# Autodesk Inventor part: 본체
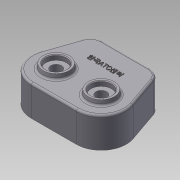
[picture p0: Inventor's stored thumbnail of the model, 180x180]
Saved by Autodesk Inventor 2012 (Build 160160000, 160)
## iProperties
Created: 2014-12
Part Number: 본체
Material: 알루미늄-6061
Document SubType Name: Modeling
Designer: Administrator
Density: 2.71 g/cm^3
Mass: 613.436 g
Surface Area: 665.18 cm^2
Volume: 226.36 cm^3
Author: Administrator
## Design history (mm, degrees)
sketch "스케치1"
  geometry: L1 (0, 36)-(-34.162, 36); L2 (0, 36)-(34.162, 36); L3 (-51.181, 23.862)-(-66.565, -20.803); L4 (51.181, 23.862)-(66.565, -20.803); L5 (32.527, -68.527)-(-32.527, -68.527); A1 r 36 centre (-32.527, -32.527) between (-66.565, -20.803) and (-32.527, -68.527); A2 r 36 centre (32.527, -32.527) between (32.527, -68.527) and (66.565, -20.803); A3 r 18 centre (-34.162, 18) between (-34.162, 36) and (-51.181, 23.862); A4 r 18 centre (34.162, 18) between (51.181, 23.862) and (34.162, 36); 3 further points
  constraints: 10 end point, 8 point on circle, 7 tangent, 4 centre point, 4 point on line, 1 collinear, 1 equal radius, 1 parallel
extrude "돌출1" new body sketch "스케치1" distance "d9" = 44; taper "d10" = 0 deg
sketch "스케치2"
  geometry: L1 (34.162, 31)-(-34.162, 31); L2 (-46.453, 22.233)-(-61.837, -22.432); L3 (-32.527, -63.527)-(32.527, -63.527); L4 (61.837, -22.432)-(46.453, 22.233); A1 r 13 centre (-34.162, 18) between (-34.162, 31) and (-46.453, 22.233); A2 r 31 centre (-32.527, -32.527) between (-61.837, -22.432) and (-32.527, -63.527); A3 r 31 centre (32.527, -32.527) between (32.527, -63.527) and (61.837, -22.432); A4 r 13 centre (34.162, 18) between (46.453, 22.233) and (34.162, 31); 6 further points
  constraints: 8 end point, 8 point on circle, 4 centre point
extrude "돌출2" cut sketch "스케치2" distance "d12" = 34; taper "d13" = 0 deg
sketch "스케치3"
  geometry: C1 r 24 at (0, 0); 1 further point
  constraints: 1 centre point, 1 coincident
  dimensions: "d14" = 48 diameter of C1
extrude "돌출3" join sketch "스케치3" distance "d15" = 11; taper "d16" = 0 deg
sketch "스케치4"
  geometry: C1 r 24 at (0, 0) reference; C2 r 20 at (0, 0)
  constraints: 1 centre point, 1 coincident
  dimensions: "d17" = 40 diameter of C2
extrude "돌출4" cut sketch "스케치4" distance "d18" = 12; taper "d19" = 0 deg
sketch "스케치5"
  geometry: C1 r 20 at (0, 0) reference; C2 r 10 at (0, 0)
  constraints: 1 centre point, 1 coincident
  dimensions: "d20" = 20 diameter of C2
extrude "돌출5" cut sketch "스케치5" distance "d21" = 3; taper "d22" = 0 deg
sketch "스케치6"
  geometry: C1 r 24 at (-32.527, -32.527); A1 r 31 centre (-32.527, -32.527) between (-61.837, -22.432) and (-32.527, -63.527) reference
  constraints: 1 centre point, 1 coincident
  dimensions: "d23" = 48 diameter of C1
extrude "돌출6" join sketch "스케치6" distance "d24" = 11; taper "d25" = 0 deg
sketch "스케치7"
  geometry: C1 r 17.5 at (-32.527, -32.527); A1 r 24 centre (-32.527, -32.527) between (-21.111, -11.416) and (-11.416, -21.111) reference
  constraints: 1 centre point, 1 coincident
  dimensions: "d26" = 35 diameter of C1
extrude "돌출7" cut sketch "스케치7" distance "d27" = 11; taper "d28" = 0 deg
sketch "스케치8"
  geometry: C1 r 24 at (32.527, -32.527); A1 r 31 centre (32.527, -32.527) between (32.527, -63.527) and (61.837, -22.432) reference
  constraints: 1 centre point, 1 coincident
  dimensions: "d29" = 48 diameter of C1
extrude "돌출8" join sketch "스케치8" distance "d30" = 11; taper "d31" = 0 deg
sketch "스케치9"
  geometry: C1 r 17.5 at (32.527, -32.527); A1 r 24 centre (32.527, -32.527) between (11.416, -21.111) and (21.111, -11.416) reference
  constraints: 1 centre point, 1 coincident
  dimensions: "d32" = 35 diameter of C1
extrude "돌출9" cut sketch "스케치9" distance "d33" = 11; taper "d34" = 0 deg
sketch "스케치10"
  geometry: C1 r 20 at (-32.527, -32.527); A1 r 36 centre (-32.527, -32.527) between (-66.565, -20.803) and (-32.527, -68.527) reference; 1 further point
  constraints: 1 centre point, 1 coincident
  dimensions: "d35" = 40 diameter of C1
extrude "돌출10" join sketch "스케치10" distance "d36" = 7; taper "d37" = -10 deg
sketch "스케치11"
  geometry: C1 r 18.766 at (0, 0) reference; C2 r 15 at (0, 0); 1 further point
  constraints: 1 centre point, 1 coincident
  dimensions: "d38" = 30 diameter of C2
extrude "돌출11" cut sketch "스케치11" distance "d39" = 7; taper "d40" = 0 deg
sketch "스케치12"
  geometry: C1 r 15 at (0, 0) reference; C2 r 7.75 at (0, 0); 1 further point
  constraints: 1 centre point, 1 coincident
  dimensions: "d41" = 15.5 diameter of C2
extrude "돌출12" cut sketch "스케치12" distance "d42" = 10; taper "d43" = 0 deg
sketch "스케치13"
  geometry: C1 r 20 at (32.527, -32.527); A1 r 36 centre (32.527, -32.527) between (32.527, -68.527) and (66.565, -20.803) reference; 1 further point
  constraints: 1 centre point, 1 coincident
  dimensions: "d44" = 40 diameter of C1
extrude "돌출13" join sketch "스케치13" distance "d45" = 7; taper "d46" = -10 deg
sketch "스케치14"
  geometry: C1 r 18.766 at (0, 0) reference; C2 r 15 at (0, 0); 1 further point
  constraints: 1 centre point, 1 coincident
  dimensions: "d47" = 30 diameter of C2
extrude "돌출14" cut sketch "스케치14" distance "d48" = 7; taper "d49" = 0 deg
sketch "스케치15"
  geometry: C1 r 15 at (0, 0) reference; C2 r 7.75 at (0, 0); 1 further point
  constraints: 1 centre point, 1 coincident
  dimensions: "d50" = 15.5 diameter of C2
extrude "돌출15" cut sketch "스케치15" distance "d51" = 15.5; taper "d52" = 0 deg
sketch "스케치16"
  geometry: L1 (-32.527, -63.527)-(32.527, -63.527) reference; A1 r 8 centre (0, -63.527) between (8, -63.527) and (-8, -63.527)
  constraints: 2 point on circle, 2 point on line, 1 centre point, 1 midpoint
  dimensions: "d53" = 16 diameter of A1
extrude "돌출16" join sketch "스케치16" distance "d54" = 34; taper "d55" = 0 deg
sketch "스케치17"
  geometry: L1 (61.837, -22.432)-(46.453, 22.233) reference; L2 (-46.453, 22.233)-(-61.837, -22.432) reference; A1 r 8 centre (51.7, 7) between (49.095, 14.564) and (54.305, -0.564); A2 r 8 centre (-51.7, 7) between (-54.305, -0.564) and (-49.095, 14.564)
  constraints: 6 point on line, 4 point on circle, 2 centre point
  dimensions: "d58" = 16 diameter of A1; "d59" = 16 diameter of A2
extrude "돌출17" join sketch "스케치17" distance "d60" = 34; taper "d61" = 0 deg
sketch "스케치18"
  geometry: A1 r 8 centre (51.7, 7) between (49.095, 14.564) and (54.305, -0.564) reference; A2 r 8 centre (0, -63.527) between (8, -63.527) and (-8, -63.527) reference; A3 r 8 centre (-51.7, 7) between (-54.305, -0.564) and (-49.095, 14.564) reference; 4 further points
  constraints: 3 coincident
hole "구멍1" sketch "스케치18" at (-51.7, 7), (0, -63.527), (51.7, 7) diameter "d62" = 4.134; stored, may be unused: countersink angle "d66" = 90 deg, drill point angle "d68" = 118 deg; dims "d63" = 20, "d64" = 4, "d65" = 2, "d67" = 23
fillet "모깎기1" dims "d69" = 0.3
fillet "모깎기2" dims "d70" = 0.1
fillet "모깎기3" dims "d71" = 0.3
fillet "모깎기4" dims "d72" = 3
fillet "모깎기5" dims "d73" = 3
fillet "모깎기6" dims "d74" = 3
fillet "모깎기7" dims "d75" = 3
fillet "모깎기8" dims "d76" = 3
chamfer "모따기1" distance "d77" = 1; stored, may be unused: second distance "d78" = 2, angle "d79" = 45 deg
sketch "스케치19"
  geometry: L1 (-24.881, 9.605)-(24.894, 9.605); L2 (24.894, 9.605)-(24.894, 2.4); L3 (24.894, 2.4)-(-24.881, 2.4); L4 (-24.881, 2.4)-(-24.881, 9.605); 1 further point
  constraints: 2 other
feature "엠보싱1" sketch "스케치19" dims "d83" = 1, "d84" = 0
fillet "모깎기9" dims "d85" = 3
node "솔리드1"
